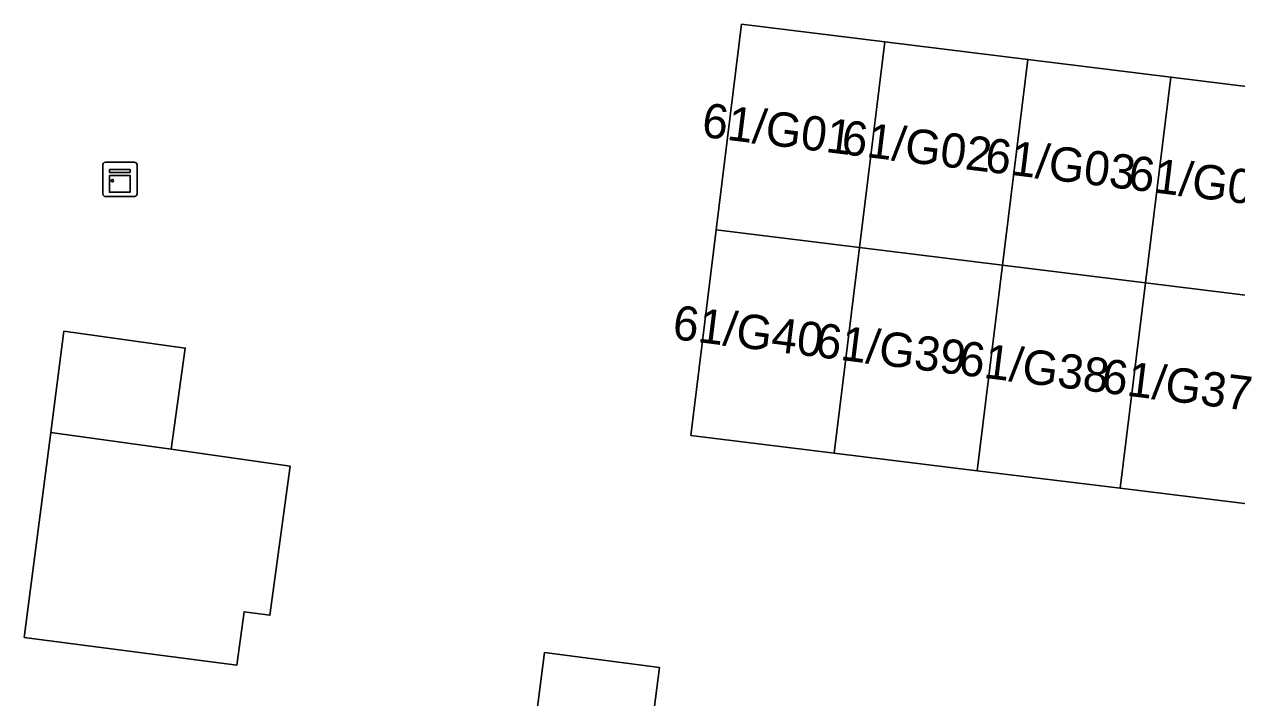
# Model space of a CAD drawing. Extents: x 161692 to 162379, y 380760 to 381678.
# Drawn here: x 161832.88 to 161868.24, y 381354.67 to 381374.31 of the extents above; entities that cross this region are included whole.
import ezdxf

# ---------------------------------------------------------------- set-up
doc = ezdxf.new("R2010")
doc.units = 0
for name, color, linetype in [('IMGEO_Erf', 7, 'Continuous'), ('IMGEO_Kast', 7, 'Continuous'), ('IMGEO_Pand', 7, 'Continuous'), ('IMGEO_Pand_nummerreeks', 7, 'Continuous')]:
    doc.layers.add(name, color=color, linetype=linetype)

msp = doc.modelspace()

# ---------------------------------------------------------------- linework, layer by layer
at = {"layer": 'IMGEO_Erf'}
for points in [[(161869.015, 381360.264), (161864.842, 381360.778), (161860.669, 381361.292), (161856.496, 381361.806), (161852.32, 381362.32), (161853.06, 381368.315), (161853.799, 381374.309), (161857.972, 381373.795), (161862.145, 381373.281), (161866.318, 381372.767), (161870.492, 381372.253)], [(161847.403, 381350.995), (161848.046, 381355.988), (161851.4, 381355.556), (161850.806, 381350.952)]]:
    msp.add_lwpolyline(points, dxfattribs=at)
msp.add_lwpolyline([(161840.041, 381357.078), (161839.288, 381357.18), (161839.078, 381355.624), (161832.876, 381356.432), (161833.655, 381362.409), (161834.033, 381365.358), (161837.57, 381364.869), (161837.162, 381361.916), (161840.628, 381361.428)], close=True, dxfattribs=at)
at = {"layer": 'IMGEO_Kast'}
for p, q in [((161835.242, 381370.285), (161836.083, 381370.285)), ((161836.083, 381370.285), (161835.242, 381370.285)), ((161835.167, 381369.36), (161835.167, 381370.201)), ((161835.167, 381370.201), (161835.167, 381369.36)), ((161836.167, 381370.21), (161836.167, 381369.369)), ((161836.167, 381369.369), (161836.167, 381370.21)), ((161836.092, 381369.285), (161835.251, 381369.285)), ((161835.251, 381369.285), (161836.092, 381369.285))]:
    msp.add_line(p, q, dxfattribs=at)
for points in [[(161835.362, 381370.075), (161835.962, 381370.075), (161835.962, 381369.99), (161835.362, 381369.99), (161835.362, 381370.075)], [(161835.362, 381369.9), (161835.962, 381369.9), (161835.962, 381369.411), (161835.362, 381369.411), (161835.362, 381369.9)]]:
    msp.add_lwpolyline(points, dxfattribs=at)
msp.add_circle((161835.446, 381369.749), 0.0377, dxfattribs=at)
for centre, start, end in [((161835.245, 381370.207), 92.4484, 184.2845), ((161835.245, 381370.207), 92.4484, 184.2845), ((161836.089, 381370.207), 2.4484, 94.2845), ((161836.089, 381370.207), 2.4484, 94.2845), ((161835.245, 381369.363), 182.4484, 274.2845), ((161835.245, 381369.363), 182.4484, 274.2845), ((161836.089, 381369.363), 272.4484, 4.2845), ((161836.089, 381369.363), 272.4484, 4.2845)]:
    msp.add_arc(centre, 0.0779, start, end, dxfattribs=at)
at = {"layer": 'IMGEO_Pand'}
for points in [[(161857.234, 381367.8), (161857.972, 381373.795), (161853.799, 381374.309), (161853.06, 381368.315)], [(161861.407, 381367.285), (161862.145, 381373.281), (161857.972, 381373.795), (161857.234, 381367.8)], [(161865.58, 381366.77), (161866.318, 381372.767), (161862.145, 381373.281), (161861.407, 381367.285)], [(161865.58, 381366.77), (161869.753, 381366.255), (161870.492, 381372.253), (161866.318, 381372.767)], [(161857.234, 381367.8), (161853.06, 381368.315), (161852.32, 381362.32), (161856.496, 381361.806)], [(161856.496, 381361.806), (161860.669, 381361.292), (161861.407, 381367.285), (161857.234, 381367.8)], [(161864.842, 381360.778), (161865.58, 381366.77), (161861.407, 381367.285), (161860.669, 381361.292)], [(161864.842, 381360.778), (161869.015, 381360.264), (161869.753, 381366.255), (161865.58, 381366.77)], [(161837.57, 381364.869), (161834.033, 381365.358), (161833.655, 381362.409), (161837.162, 381361.916)], [(161840.628, 381361.428), (161837.162, 381361.916), (161833.655, 381362.409), (161832.876, 381356.432), (161839.078, 381355.624), (161839.288, 381357.18), (161840.041, 381357.078)], [(161851.4, 381355.556), (161848.046, 381355.988), (161847.403, 381350.995), (161850.756, 381350.563), (161850.806, 381350.952)]]:
    msp.add_lwpolyline(points, close=True, dxfattribs=at)

# ---------------------------------------------------------------- texts
at = {"layer": 'IMGEO_Pand_nummerreeks'}
for s, rotation, p in [('61/G01', 352.9716, (161852.607, 381371.032)), ('61/G02', 352.9716, (161856.674, 381370.53)), ('61/G03', 352.9716, (161860.863, 381370.014)), ('61/G04', 352.9716, (161865.045, 381369.498)), ('61/G40', 352.8838, (161851.752, 381365.136)), ('61/G39', 352.8838, (161855.917, 381364.616)), ('61/G38', 352.8838, (161860.095, 381364.094)), ('61/G37', 352.8838, (161864.264, 381363.574))]:
    msp.add_text(s, height=1, rotation=rotation, dxfattribs=at).set_placement(p)

doc.saveas('drawing.dxf')
